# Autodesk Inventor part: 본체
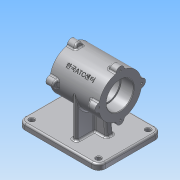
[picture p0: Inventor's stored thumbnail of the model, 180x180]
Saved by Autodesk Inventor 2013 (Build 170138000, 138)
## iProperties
Created: 2015-12
Part Number: 본체
Material: 알루미늄 6061
Document SubType Name: Modeling
Designer: Administrator
Density: 2.71 g/cm^3
Mass: 1146.17 g
Surface Area: 790.525 cm^2
Volume: 422.942 cm^3
Author: Administrator
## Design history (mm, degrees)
sketch "스케치1"
  geometry: L1 (-68, 55)-(48, 55); L2 (60, 43)-(60, -43); L3 (48, -55)-(-68, -55); L4 (-80, -43)-(-80, 43); C1 r 4 at (-68, 43); C2 r 4 at (-68, -43); C3 r 4 at (48, -43); C4 r 4 at (48, 43); A1 r 12 centre (-68, 43) between (-68, 55) and (-80, 43); A2 r 12 centre (-68, -43) between (-80, -43) and (-68, -55); A3 r 12 centre (48, -43) between (48, -55) and (60, -43); A4 r 12 centre (48, 43) between (60, 43) and (48, 55); 5 further points
  constraints: 8 centre point, 8 end point, 8 point on circle, 8 tangent, 6 equal radius, 6 point on line, 4 coincident, 2 parallel, 1 horizontal, 1 horizontal alignment, 1 midpoint, 1 perpendicular
  dimensions: "d0" = 110 distance of point (60, 55) point (60, -55); "d2" = 140 distance of point (-80, 55) point (60, 55); "d3" = 80 distance from line of point (0, 0) L4; "d4" = 12 radius of A1; "d5" = 8 diameter of C1
extrude "돌출1" new body sketch "스케치1" distance "d6" = 10; taper "d7" = 0 deg
chamfer "모따기1" distance "d8" = 1; stored, may be unused: second distance "d9" = 2, angle "d10" = 45 deg
chamfer "모따기2" distance "d11" = 1; stored, may be unused: second distance "d12" = 2, angle "d13" = 45 deg
chamfer "모따기3" distance "d14" = 1; stored, may be unused: second distance "d15" = 2, angle "d16" = 45 deg
chamfer "모따기4" distance "d17" = 1; stored, may be unused: second distance "d18" = 2, angle "d19" = 45 deg
sketch "스케치2"
  geometry: L1 (43, 0)-(-43, 0) reference; C1 r 37 at (0, 80); 2 further points
  constraints: 1 centre point, 1 midpoint, 1 vertical alignment
  dimensions: "d20" = 80 distance from line of L1 C1.centre; "d21" = 74 diameter of C1
extrude "돌출2" join sketch "스케치2" stored distance "d22" = 85; taper "d23" = 0 deg
fillet "모깎기1" dims "d29" = 3
sketch "스케치4"
  geometry: L1 (4, -37)-(-4, -37); L2 (-4, -37)-(-4, 37); L3 (-4, 37)-(4, 37); L4 (4, 37)-(4, -37); 3 further points
  constraints: 8 end point, 2 midpoint, 2 parallel, 1 horizontal, 1 horizontal alignment, 1 perpendicular, 1 vertical alignment
  dimensions: "d32" = 8 distance of L2.end L3.end; "d34" = 74 distance of L3.end L1.start
extrude "돌출4" join sketch "스케치4" stored distance "d35" = 15; taper "d36" = 0 deg
sketch "스케치5"
  geometry: L1 (42.5, 43)-(-42.5, 43) reference; L2 (-48, 10)-(68, 10) reference; L3 (-25, 10)-(-19.475, 55); L4 (-19.475, 55)-(19.475, 55); L5 (19.475, 55)-(25, 10); L6 (-25, 10)-(25, 10); 2 further points
  constraints: 8 end point, 2 point on line, 1 collinear, 1 equal length, 1 midpoint, 1 parallel, 1 vertical alignment
  dimensions: "d37" = 97 deg angle of L2 L3; "d38" = 50 distance of L3.start L5.end; "d40" = 45 distance between parallel lines of L2 L4
extrude "돌출5" join sketch "스케치5" stored distance "d41" = 12; taper "d42" = 0 deg
fillet "모깎기2" dims "d43" = 3
fillet "모깎기3" dims "d44" = 3
fillet "모깎기4" dims "d45" = 3
fillet "모깎기5" dims "d46" = 3
fillet "모깎기6" dims "d47" = 3
hole "구멍1" diameter "d50" = 42; stored, may be unused: countersink angle "d54" = 90 deg, drill point angle "d56" = 118 deg; dims "d51" = 6, "d52" = 47, "d53" = 22, "d55" = 8, "d66" = 10, "d67" = 10
hole "구멍2" diameter "d59" = 47; stored, may be unused: countersink angle "d63" = 90 deg, drill point angle "d65" = 0 deg; dims "d57" = 10, "d58" = 10, "d60" = 6, "d61" = 47, "d62" = 22, "d64" = 22
chamfer "모따기5" distance "d68" = 1; stored, may be unused: second distance "d69" = 2, angle "d70" = 45 deg
chamfer "모따기6" distance "d71" = 1; stored, may be unused: second distance "d72" = 2, angle "d73" = 45 deg
fillet "모깎기7" dims "d74" = 0.3
node "작업 평면3"
  node "작업 평면2"
sketch "스케치6"
  geometry: L1 (-24.887, 2.435)-(24.887, 2.435); L2 (24.887, 2.435)-(24.887, -2.435); L3 (24.887, -2.435)-(-24.887, -2.435); L4 (-24.887, -2.435)-(-24.887, 2.435); L5 (-42.5, 37)-(-42.5, -37) reference; 5 further points
  constraints: 3 midpoint, 2 horizontal alignment, 2 vertical alignment, 1 horizontal, 2 other
  dimensions: "d77" = 67.38738 distance between parallel lines of L2 L5; "d78" = 4.86969 distance between parallel lines of L1 L3
feature "엠보싱1" sketch "스케치6" dims "d8" = 1, "d79" = 0.5, "d80" = 0
sketch "스케치8"
  geometry: C1 r 24.5 at (0, 0) reference; A1 r 37 centre (0, 0) between (-37, 0) and (-36.338, -6.969) reference; A2 r 7 centre (-37, 0) between (-36.338, 6.969) and (-36.338, -6.969); 1 further point
  constraints: 5 point on circle, 1 centre point, 1 horizontal alignment
  dimensions: "d95" = 14 diameter of A2
extrude "돌출7" new body sketch "스케치8" distance "d97" = 15; taper "d98" = 0 deg
node "작업 평면10"
  node "작업축8"
feature "분할2"
feature "분할3"
feature "분할4"
feature "분할5"
feature "결합1"
  node "솔리드4"
fillet "모깎기8" dims "d106" = 3
fillet "모깎기9" dims "d107" = 3
hole "구멍3" diameter "d110" = 3.242; stored, may be unused: countersink angle "d114" = 90 deg, drill point angle "d116" = 118 deg; dims "d108" = 10, "d109" = 10, "d111" = 9, "d112" = 47, "d113" = 22, "d115" = 11
hole "구멍4" diameter "d119" = 3.242; stored, may be unused: countersink angle "d123" = 90 deg, drill point angle "d125" = 118 deg; dims "d117" = 10, "d118" = 10, "d120" = 9, "d121" = 47, "d122" = 22, "d124" = 11
hole "구멍5" diameter "d128" = 3.242; stored, may be unused: countersink angle "d132" = 90 deg, drill point angle "d134" = 118 deg; dims "d126" = 10, "d127" = 10, "d129" = 9, "d130" = 47, "d131" = 22, "d133" = 11
hole "구멍6" diameter "d137" = 3.242; stored, may be unused: countersink angle "d141" = 90 deg, drill point angle "d143" = 118 deg; dims "d135" = 10, "d136" = 10, "d138" = 9, "d139" = 47, "d140" = 22, "d142" = 11
node "솔리드1"
pattern_circular "원형 패턴2" dims angle "d104" = 360 deg
mirror "대칭2"
mirror "대칭3"
node "작업축2"
node "투영된 루프2"
node "작업 평면11"
node "작업 평면12"
node "작업 평면13"
other parameters: "d76" = 135 deg, "d99" = -20 deg
